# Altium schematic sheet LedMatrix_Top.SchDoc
size A4; Organization: Altium Limited; Address1: L3, 12a Rodborough Rd; Address2: Frenchs Forest; Address3: NSW; Address4: Australia 2086; DocumentNumber: 1; SheetNumber: 1; SheetTotal: 6
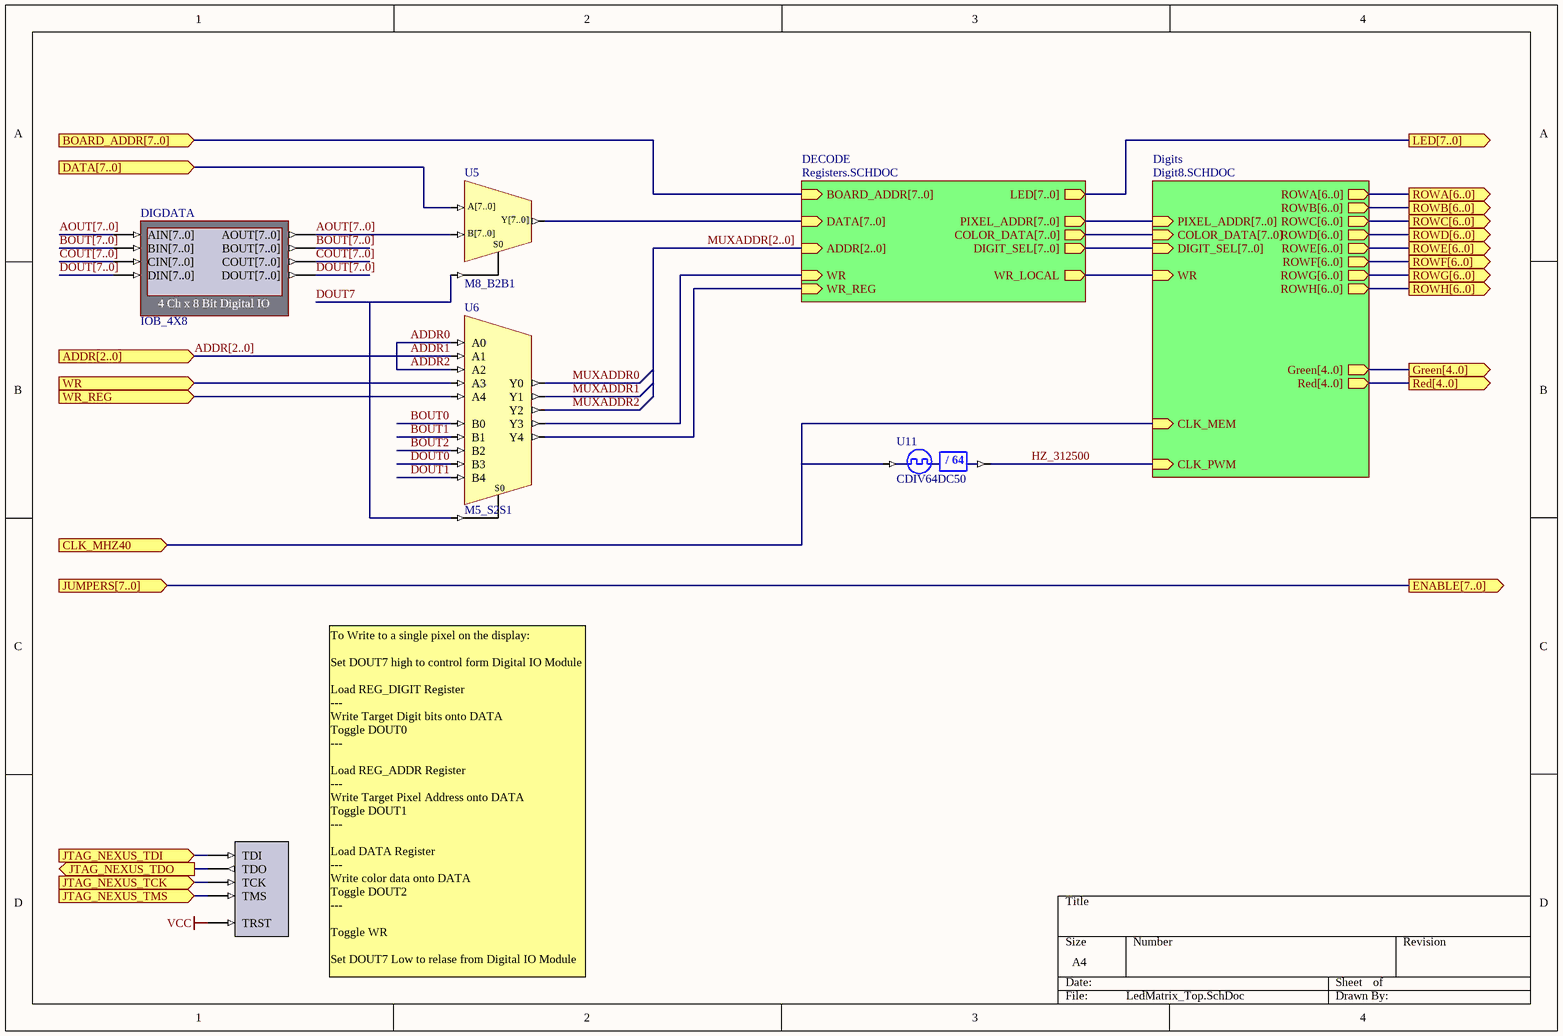
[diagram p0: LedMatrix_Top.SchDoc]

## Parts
DIGDATA  IOB_4X8
NEXUS_JTAG_PORT1  NEXUS_JTAG_PORT  (value not drawn)
U5  M8_B2B1
U6  M5_S2S1
U11  CDIV64DC50

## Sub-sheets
DECODE = Registers.SCHDOC: WR (in), ADDR[2..0] (in), BOARD_ADDR[7..0] (in), PIXEL_ADDR[7..0] (out), DATA[7..0] (in), COLOR_DATA[7..0] (out), DIGIT_SEL[7..0] (out), WR_LOCAL (out), LED[7..0] (out), WR_REG (in)
Digits = Digit8.SCHDOC: ROWB[6..0] (out), ROWC[6..0] (out), ROWD[6..0] (out), ROWF[6..0] (out), ROWG[6..0] (out), ROWH[6..0] (out), ROWE[6..0] (out), ROWA[6..0] (out), CLK_MEM (in), CLK_PWM (in), Red[4..0] (out), Green[4..0] (out), PIXEL_ADDR[7..0] (in), COLOR_DATA[7..0] (in), DIGIT_SEL[7..0] (in), WR (in)

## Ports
ADDR[2..0] (in), BOARD_ADDR[7..0] (in), CLK_MHZ40 (in), DATA[7..0] (in), ENABLE[7..0] (out), Green[4..0] (out), JTAG_NEXUS_TCK (in), JTAG_NEXUS_TDI (in), JTAG_NEXUS_TDO (out), JTAG_NEXUS_TMS (in), JUMPERS[7..0] (in), LED[7..0] (out), Red[4..0] (out), ROWA[6..0] (out), ROWB[6..0] (out), ROWC[6..0] (out), ROWD[6..0] (out), ROWE[6..0] (out), ROWF[6..0] (out), ROWG[6..0] (out), ROWH[6..0] (out), WR (in), WR_REG (in)

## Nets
VCC: NEXUS_JTAG_PORT1.TRST
ADDR0: U6.A0
ADDR1: U6.A1
ADDR2: U6.A2
BOUT0: U6.B0
BOUT1: U6.B1
BOUT2: U6.B2
CLK_MHZ40: U11.CLKIN ; port CLK_MHZ40, sheet Digits/CLK_MEM
DOUT0: U6.B3
DOUT1: U6.B4
DOUT7: U5.S0 U6.S0
HZ_312500: U11.CLKDV ; sheet Digits/CLK_PWM
JTAG_NEXUS_TCK: NEXUS_JTAG_PORT1.TCK ; port JTAG_NEXUS_TCK
JTAG_NEXUS_TDI: NEXUS_JTAG_PORT1.TDI ; port JTAG_NEXUS_TDI
JTAG_NEXUS_TDO: NEXUS_JTAG_PORT1.TDO ; port JTAG_NEXUS_TDO
JTAG_NEXUS_TMS: NEXUS_JTAG_PORT1.TMS ; port JTAG_NEXUS_TMS
MUXADDR0: U6.Y0
MUXADDR1: U6.Y1
MUXADDR2: U6.Y2
WR: U6.A3 ; port WR
WR_REG: U6.A4 ; port WR_REG
NetU6_Y3: U6.Y3 ; sheet DECODE/WR
NetU6_Y4: U6.Y4 ; sheet DECODE/WR_REG
(unnamed): sheet Digits/WR, sheet DECODE/WR_LOCAL

Not connected (* = marked no-connect by the designer): DIGDATA AIN[7..0] AOUT[7..0] BIN[7..0] BOUT[7..0] CIN[7..0] COUT[7..0] DIN[7..0] DOUT[7..0]; U5 A[7..0] B[7..0] Y[7..0]

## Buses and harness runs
bus ADDR[2..0] = port ADDR[2..0]
bus AOUT[7..0]
bus BOUT[7..0]
bus COUT[7..0]
bus DOUT[7..0]
bus MUXADDR[2..0] = sheet DECODE/ADDR[2..0]
bus port BOARD_ADDR[7..0] = sheet DECODE/BOARD_ADDR[7..0]
bus port ENABLE[7..0] = port JUMPERS[7..0]
bus port Green[4..0] = sheet Digits/Green[4..0]
bus port LED[7..0] = sheet DECODE/LED[7..0]
bus port Red[4..0] = sheet Digits/Red[4..0]
bus port ROWA[6..0] = sheet Digits/ROWA[6..0]
bus port ROWB[6..0] = sheet Digits/ROWB[6..0]
bus port ROWC[6..0] = sheet Digits/ROWC[6..0]
bus port ROWD[6..0] = sheet Digits/ROWD[6..0]
bus port ROWE[6..0] = sheet Digits/ROWE[6..0]
bus port ROWF[6..0] = sheet Digits/ROWF[6..0]
bus port ROWG[6..0] = sheet Digits/ROWG[6..0]
bus port ROWH[6..0] = sheet Digits/ROWH[6..0]
bus sheet DECODE/COLOR_DATA[7..0] = sheet Digits/COLOR_DATA[7..0]
bus sheet DECODE/DIGIT_SEL[7..0] = sheet Digits/DIGIT_SEL[7..0]
bus sheet DECODE/PIXEL_ADDR[7..0] = sheet Digits/PIXEL_ADDR[7..0]

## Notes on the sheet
- To Write to a single pixel on the display:
  Set DOUT7 high to control form Digital IO Module
  Load REG_DIGIT Register
  ---
  Write Target Digit bits onto DATA
  Toggle DOUT0
  ---
  Load REG_ADDR Register
  ---
  Write Target Pixel Address onto DATA
  Toggle DOUT1
  ---
  Load DATA Register
  ---
  Write color data onto DATA
  Toggle DOUT2
  ---
  Toggle WR
  Set DOUT7 Low to relase from Digital IO Module

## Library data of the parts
DIGDATA = IOB_4X8: 4 Ch x 8 Bit Digital IO; NEXUS_CORE: Instrument; NEXUS_JTAG_DEVICE: True; NEXUS_JTAG_ORDER: 0
NEXUS_JTAG_PORT1 = NEXUS_JTAG_PORT: Nexus Processor JTAG Chain Connector; NEXUS_JTAG_CONNECTOR: True
U5 = M8_B2B1: 2x8-Bit Bus to 1x8-Bit Bus Multiplexer; ArchiveName: GENERIC
U6 = M5_S2S1: 2x5-Single Wire to 2x5-Single Wire Multiplexer; ArchiveName: GENERIC; VHDLIB_SIM: GENERIC_LIB
U11 = CDIV64DC50: Clock Divider by 64 with 50% Duty Cycle Output; ArchiveName: GENERIC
